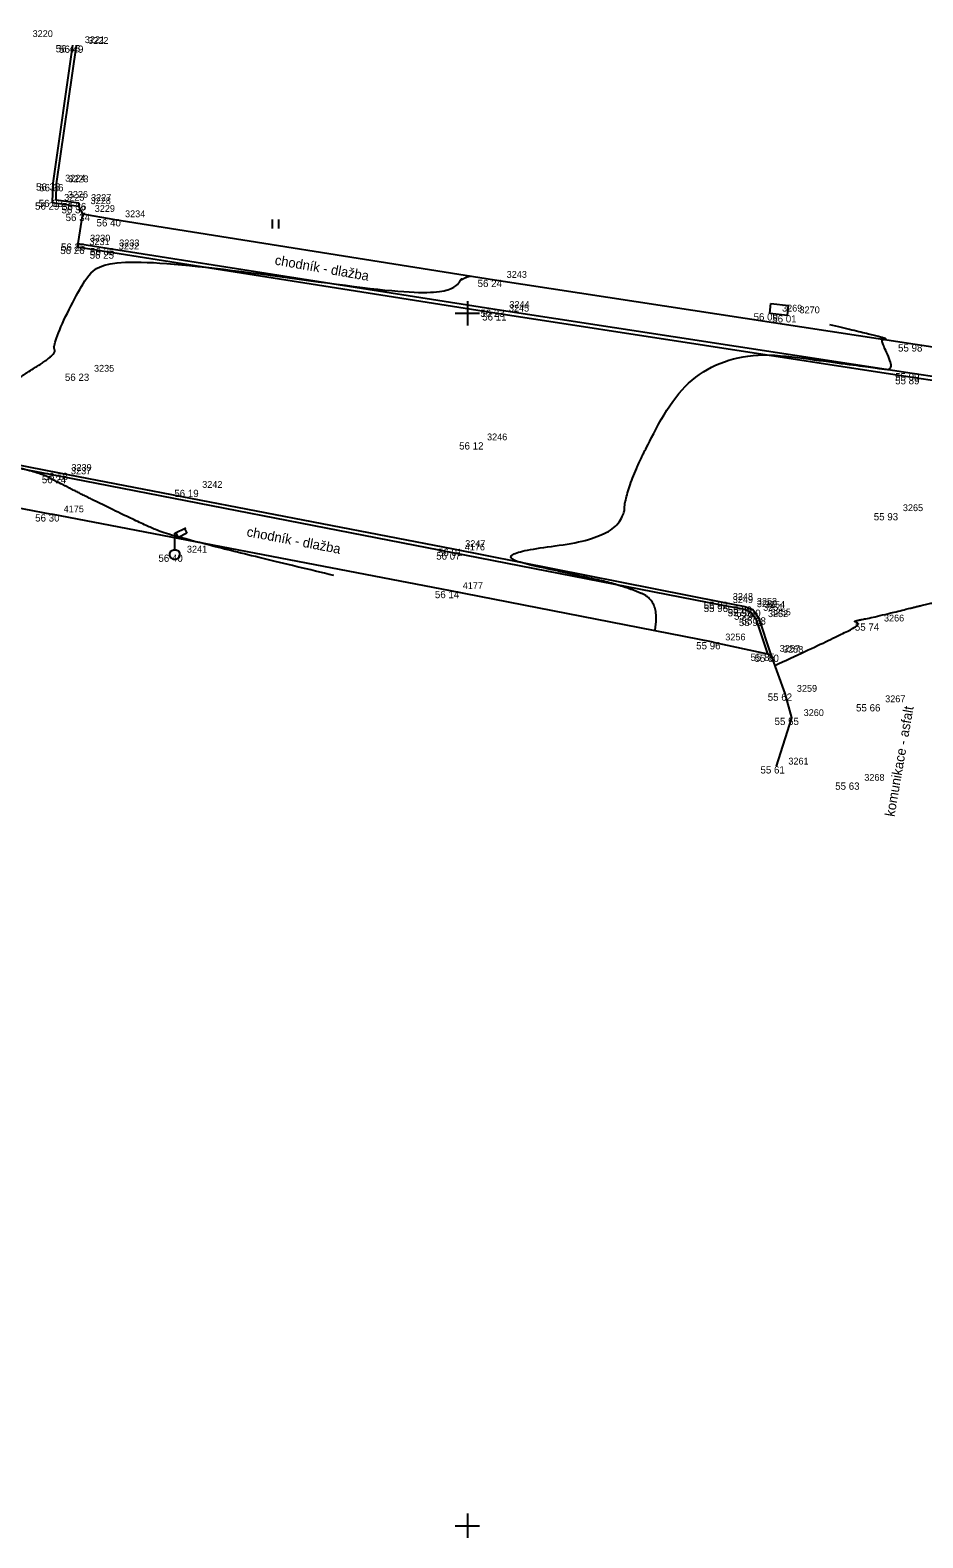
# Model space of a CAD drawing. Extents: x -704017 to -701500, y -1008977 to -1008450.
# Drawn here: x -702268 to -702231.2, y -1008850.5 to -1008788.3 of the extents above; entities that cross this region are included whole.
import ezdxf

# ---------------------------------------------------------------- set-up
doc = ezdxf.new("R2010")
doc.units = 0
for name, color, linetype in [('Z_body', 7, 'Continuous'), ('Z_body_cisla', 7, 'Continuous'), ('Z_body_vysky', 7, 'Continuous'), ('Z_chodnik', 7, 'Continuous'), ('Z_hekt_sit', 7, 'Continuous'), ('Z_komunikace', 7, 'Continuous'), ('Z_obruby', 7, 'Continuous'), ('Z_popis', 7, 'Continuous'), ('Z_site_znaky_pilire', 7, 'Continuous'), ('Z_site_znaky_VO', 7, 'Continuous'), ('Z_vrstevnice_hlavni', 7, 'Continuous'), ('Z_vrstevnice_vedlejsi', 7, 'Continuous')]:
    doc.layers.add(name, color=color, linetype=linetype)

# ---------------------------------------------------------------- blocks, each defined once
blk = doc.blocks.new('POINT_DISPLAY')
blk.add_line((0, 0), (0, 0))
blk = doc.blocks.new('Z306')
for p, q in [((-0.13, 0.17), (-0.13, -0.2)), ((0.13, 0.17), (0.13, -0.2))]:
    blk.add_line(p, q)
blk = doc.blocks.new('Z13')
for p, q in [((0, 0.88), (0.45, 1.1)), ((0, 0.2), (0, 0.88)), ((0.15, 0.7), (0.05, 0.9)), ((0.5, 0.88), (0.15, 0.7)), ((0.4, 1.07), (0.5, 0.88)), ((-0.2, 0.05), (-0.15, 0.15)), ((-0.2, -0.05), (-0.2, 0.05)), ((-0.15, 0.15), (-0.05, 0.2)), ((-0.05, 0.2), (0.05, 0.2)), ((0.05, 0.2), (0.15, 0.15)), ((0.15, 0.15), (0.2, 0.05)), ((0.2, 0.05), (0.2, -0.05)), ((-0.15, -0.15), (-0.2, -0.05)), ((-0.05, -0.2), (-0.15, -0.15)), ((0.05, -0.2), (-0.05, -0.2)), ((0.15, -0.15), (0.05, -0.2)), ((0.2, -0.05), (0.15, -0.15))]:
    blk.add_line(p, q)

msp = doc.modelspace()

# ---------------------------------------------------------------- linework, layer by layer
at = {"layer": 'Z_chodnik'}
for p, q in [((-702265.86, -1008795.9), (-702264.61, -1008796.12)), ((-702264.61, -1008796.12), (-702248.88, -1008798.62)), ((-702248.88, -1008798.62), (-702231.55, -1008801.28)), ((-702231.55, -1008801.28), (-702217.37, -1008803.4)), ((-702282.81, -1008805.22), (-702267.14, -1008808.29)), ((-702250.69, -1008811.45), (-702267.14, -1008808.29)), ((-702239.87, -1008813.56), (-702250.69, -1008811.45)), ((-702239.87, -1008813.56), (-702237.63, -1008814.04)), ((-702237.63, -1008814.04), (-702237.49, -1008814.08))]:
    msp.add_line(p, q, dxfattribs=at)
at = {"layer": 'Z_hekt_sit'}
for p, q in [((-702250, -1008799.5), (-702250, -1008800.5)), ((-702250.5, -1008800), (-702249.5, -1008800)), ((-702250, -1008849.5), (-702250, -1008850.5)), ((-702250.5, -1008850), (-702249.5, -1008850))]:
    msp.add_line(p, q, dxfattribs=at)
at = {"layer": 'Z_komunikace'}
for p, q in [((-702266.27, -1008788.94), (-702267.08, -1008794.64)), ((-702267.08, -1008794.64), (-702267.12, -1008795.43)), ((-702267.12, -1008795.43), (-702266.03, -1008795.58)), ((-702266.03, -1008795.58), (-702265.86, -1008795.9)), ((-702265.86, -1008795.9), (-702266.05, -1008797.12)), ((-702266.05, -1008797.12), (-702266.08, -1008797.26)), ((-702266.08, -1008797.26), (-702264.87, -1008797.45)), ((-702264.87, -1008797.45), (-702248.79, -1008800)), ((-702248.79, -1008800), (-702231.67, -1008802.63)), ((-702231.67, -1008802.63), (-702217.46, -1008804.76)), ((-702282.45, -1008803.56), (-702266.82, -1008806.58)), ((-702266.82, -1008806.58), (-702250.59, -1008809.71)), ((-702250.59, -1008809.71), (-702239.56, -1008811.9)), ((-702239.56, -1008811.9), (-702238.57, -1008812.09)), ((-702238.57, -1008812.09), (-702238.24, -1008812.22)), ((-702238.24, -1008812.22), (-702238, -1008812.54)), ((-702238, -1008812.54), (-702237.49, -1008814.08)), ((-702237.49, -1008814.08), (-702236.92, -1008815.68)), ((-702236.92, -1008815.68), (-702236.64, -1008816.68)), ((-702236.64, -1008816.68), (-702237.27, -1008818.68))]:
    msp.add_line(p, q, dxfattribs=at)
at = {"layer": 'Z_obruby'}
for p, q in [((-702266.13, -1008788.96), (-702266.95, -1008794.67)), ((-702266.95, -1008794.67), (-702266.97, -1008795.32)), ((-702266.97, -1008795.32), (-702266.01, -1008795.45)), ((-702266.01, -1008795.45), (-702266.03, -1008795.58)), ((-702266.05, -1008797.12), (-702264.85, -1008797.31)), ((-702264.85, -1008797.31), (-702248.77, -1008799.85)), ((-702248.77, -1008799.85), (-702231.67, -1008802.47)), ((-702231.67, -1008802.47), (-702217.42, -1008804.6)), ((-702282.44, -1008803.67), (-702266.84, -1008806.71)), ((-702266.84, -1008806.71), (-702250.61, -1008809.86)), ((-702250.61, -1008809.86), (-702239.56, -1008812.02)), ((-702239.56, -1008812.02), (-702238.57, -1008812.2)), ((-702238.57, -1008812.2), (-702238.31, -1008812.34)), ((-702238.31, -1008812.34), (-702238.11, -1008812.6)), ((-702238.11, -1008812.6), (-702237.63, -1008814.04))]:
    msp.add_line(p, q, dxfattribs=at)
at = {"layer": 'Z_site_znaky_pilire'}
for p, q in [((-702237.53, -1008800), (-702237.49, -1008799.6)), ((-702237.53, -1008800), (-702236.81, -1008800.08)), ((-702237.49, -1008799.6), (-702236.77, -1008799.68)), ((-702236.81, -1008800.08), (-702236.77, -1008799.68))]:
    msp.add_line(p, q, dxfattribs=at)
at = {"layer": 'Z_vrstevnice_hlavni'}
msp.add_open_spline([(-702242.274, -1008813.091), (-702242.033, -1008811.893), (-702243.578, -1008811.235), (-702245.453, -1008810.812), (-702249.364, -1008809.953), (-702243.612, -1008809.268), (-702243.446, -1008806.889), (-702240.23, -1008801.315), (-702233.097, -1008802.264), (-702232.382, -1008802.361), (-702232.928, -1008801.166), (-702232.883, -1008801.075), (-702232.637, -1008801.047), (-702235.057, -1008800.48)], degree=2, dxfattribs=at)
at = {"layer": 'Z_vrstevnice_vedlejsi'}
for points in [[(-702255.5, -1008810.815), (-702261.999, -1008809.278), (-702263.547, -1008808.631), (-702266.89, -1008806.973), (-702267.661, -1008806.55), (-702271.194, -1008805.765), (-702272.898, -1008805.406), (-702270.35, -1008804.888), (-702269.13, -1008803.035), (-702266.894, -1008801.685), (-702267.126, -1008801.33), (-702266.017, -1008799.003), (-702264.87, -1008797.45), (-702251.244, -1008799.459), (-702250.211, -1008798.511), (-702249.863, -1008798.464)], [(-702237.332, -1008814.524), (-702234.023, -1008813.005), (-702233.849, -1008812.762), (-702234.148, -1008812.695), (-702233.289, -1008812.551), (-702229.929, -1008811.708), (-702229.264, -1008811.892), (-702228.23, -1008812.354), (-702222.849, -1008806.003), (-702223.381, -1008803.873), (-702217.427, -1008804.627), (-702216.723, -1008804.725), (-702215.214, -1008804.954), (-702213.186, -1008804.731), (-702211.983, -1008804.24), (-702211.96, -1008804.184), (-702211.909, -1008804.059)]]:
    msp.add_open_spline(points, degree=2, dxfattribs=at)

# ---------------------------------------------------------------- block references
at = {"layer": 'Z_body'}
for p in [(-702266.27, -1008788.94), (-702266.13, -1008788.96), (-702267.08, -1008794.64), (-702266.95, -1008794.67), (-702267.12, -1008795.43), (-702266.97, -1008795.32), (-702266.03, -1008795.58), (-702266.01, -1008795.45), (-702265.86, -1008795.9), (-702264.61, -1008796.12), (-702266.08, -1008797.26), (-702266.05, -1008797.12), (-702264.87, -1008797.45), (-702264.85, -1008797.31), (-702248.88, -1008798.62), (-702248.79, -1008800), (-702248.77, -1008799.85), (-702237.53, -1008800), (-702236.81, -1008800.08), (-702231.55, -1008801.28), (-702265.89, -1008802.49), (-702231.67, -1008802.47), (-702231.67, -1008802.63), (-702249.69, -1008805.32), (-702266.84, -1008806.71), (-702266.82, -1008806.58), (-702261.43, -1008807.28), (-702267.14, -1008808.29), (-702232.55, -1008808.24), (-702262.06, -1008809.95), (-702250.61, -1008809.86), (-702250.59, -1008809.71), (-702250.69, -1008811.45), (-702239.56, -1008811.9), (-702239.56, -1008812.02), (-702238.57, -1008812.09), (-702238.57, -1008812.2), (-702238.31, -1008812.34), (-702238.24, -1008812.22), (-702238.11, -1008812.6), (-702238, -1008812.54), (-702233.33, -1008812.79), (-702239.87, -1008813.56), (-702237.63, -1008814.04), (-702237.49, -1008814.08), (-702236.92, -1008815.68), (-702233.28, -1008816.12), (-702236.64, -1008816.68), (-702237.27, -1008818.68), (-702234.14, -1008819.35)]:
    msp.add_blockref('POINT_DISPLAY', p, dxfattribs=at)
at = {"layer": 'Z_popis'}
msp.add_blockref('Z306', (-702257.91, -1008796.31), dxfattribs=at)
at = {"layer": 'Z_site_znaky_VO'}
msp.add_blockref('Z13', (-702262.06, -1008809.95), dxfattribs=at)

# ---------------------------------------------------------------- texts
at = {"layer": 'Z_body_cisla'}
for s, p in [('3220', (-702267.92, -1008788.61)), ('3221', (-702265.77, -1008788.86)), ('3222', (-702265.63, -1008788.89)), ('3224', (-702266.58, -1008794.57)), ('3223', (-702266.45, -1008794.6)), ('3225', (-702266.62, -1008795.36)), ('3226', (-702266.47, -1008795.24)), ('3228', (-702265.53, -1008795.5)), ('3227', (-702265.51, -1008795.37)), ('3229', (-702265.36, -1008795.82)), ('3234', (-702264.11, -1008796.04)), ('3231', (-702265.58, -1008797.19)), ('3230', (-702265.55, -1008797.04)), ('3232', (-702264.37, -1008797.37)), ('3233', (-702264.35, -1008797.24)), ('3243', (-702248.38, -1008798.54)), ('3244', (-702248.27, -1008799.78)), ('3245', (-702248.29, -1008799.93)), ('3269', (-702237.03, -1008799.93)), ('3270', (-702236.31, -1008800)), ('3235', (-702265.39, -1008802.41)), ('3246', (-702249.19, -1008805.24)), ('3237', (-702266.34, -1008806.64)), ('3239', (-702266.32, -1008806.5)), ('3242', (-702260.93, -1008807.2)), ('4175', (-702266.64, -1008808.21)), ('3265', (-702232.05, -1008808.16)), ('4176', (-702250.11, -1008809.78)), ('3247', (-702250.09, -1008809.64)), ('3241', (-702261.56, -1008809.87)), ('4177', (-702250.19, -1008811.37)), ('3248', (-702239.06, -1008811.82)), ('3249', (-702239.06, -1008811.95)), ('3253', (-702238.07, -1008812.02)), ('3250', (-702238.07, -1008812.12)), ('3251', (-702237.81, -1008812.27)), ('3254', (-702237.74, -1008812.15)), ('3252', (-702237.61, -1008812.53)), ('3255', (-702237.5, -1008812.46)), ('3266', (-702232.83, -1008812.71)), ('3256', (-702239.37, -1008813.49)), ('3257', (-702237.13, -1008813.96)), ('3258', (-702236.99, -1008814)), ('3259', (-702236.42, -1008815.61)), ('3260', (-702236.14, -1008816.61)), ('3267', (-702232.78, -1008816.04)), ('3261', (-702236.77, -1008818.61)), ('3268', (-702233.64, -1008819.28))]:
    msp.add_text(s, height=0.28, dxfattribs=at).set_placement(p)
at = {"layer": 'Z_body_vysky'}
for s, p in [('56 45', (-702266.97, -1008789.24)), ('56 49', (-702266.83, -1008789.26)), ('56 33', (-702267.78, -1008794.94)), ('56 36', (-702267.65, -1008794.97)), ('56 29', (-702267.82, -1008795.73)), ('56 33', (-702267.67, -1008795.62)), ('56 32', (-702266.73, -1008795.88)), ('56 36', (-702266.71, -1008795.75)), ('56 34', (-702266.56, -1008796.2)), ('56 40', (-702265.285, -1008796.42)), ('56 26', (-702266.78, -1008797.56)), ('56 26', (-702266.75, -1008797.42)), ('56 25', (-702265.57, -1008797.75)), ('56 36', (-702265.55, -1008797.61)), ('56 24', (-702249.58, -1008798.92)), ('56 23', (-702249.47, -1008800.15)), ('56 11', (-702249.39, -1008800.3)), ('56 09', (-702238.205, -1008800.3)), ('56 01', (-702237.435, -1008800.38)), ('55 98', (-702232.25, -1008801.58)), ('56 23', (-702266.59, -1008802.79)), ('55 99', (-702232.37, -1008802.77)), ('55 89', (-702232.37, -1008802.93)), ('56 12', (-702250.34, -1008805.62)), ('56 24', (-702267.54, -1008807.01)), ('56 18', (-702267.47, -1008806.88)), ('56 19', (-702262.08, -1008807.58)), ('56 30', (-702267.815, -1008808.59)), ('55 93', (-702233.25, -1008808.54)), ('56 40', (-702262.735, -1008810.25)), ('56 07', (-702251.285, -1008810.16)), ('56 01', (-702251.215, -1008810.01)), ('56 14', (-702251.34, -1008811.75)), ('55 92', (-702240.26, -1008812.2)), ('55 96', (-702240.26, -1008812.32)), ('55 89', (-702239.27, -1008812.39)), ('55 92', (-702239.27, -1008812.5)), ('55 93', (-702239.01, -1008812.64)), ('55 80', (-702238.915, -1008812.52)), ('55 93', (-702238.81, -1008812.9)), ('55 83', (-702238.7, -1008812.84)), ('55 74', (-702234.03, -1008813.09)), ('55 96', (-702240.57, -1008813.86)), ('55 85', (-702238.33, -1008814.34)), ('55 80', (-702238.165, -1008814.38)), ('55 62', (-702237.62, -1008815.98)), ('55 66', (-702233.98, -1008816.42)), ('55 55', (-702237.34, -1008816.98)), ('55 61', (-702237.92, -1008818.98)), ('55 63', (-702234.84, -1008819.65))]:
    msp.add_text(s, height=0.3, dxfattribs=at).set_placement(p)
at = {"layer": 'Z_popis'}
for s, rotation, p in [('chodník - dlažba', 350.1, (-702257.96, -1008797.99)), ('chodník - dlažba', 349.2, (-702259.12, -1008809.19)), ('komunikace - asfalt', 80.1, (-702232.4, -1008820.78))]:
    msp.add_text(s, height=0.4, rotation=rotation, dxfattribs=at).set_placement(p)

doc.saveas('drawing.dxf')
